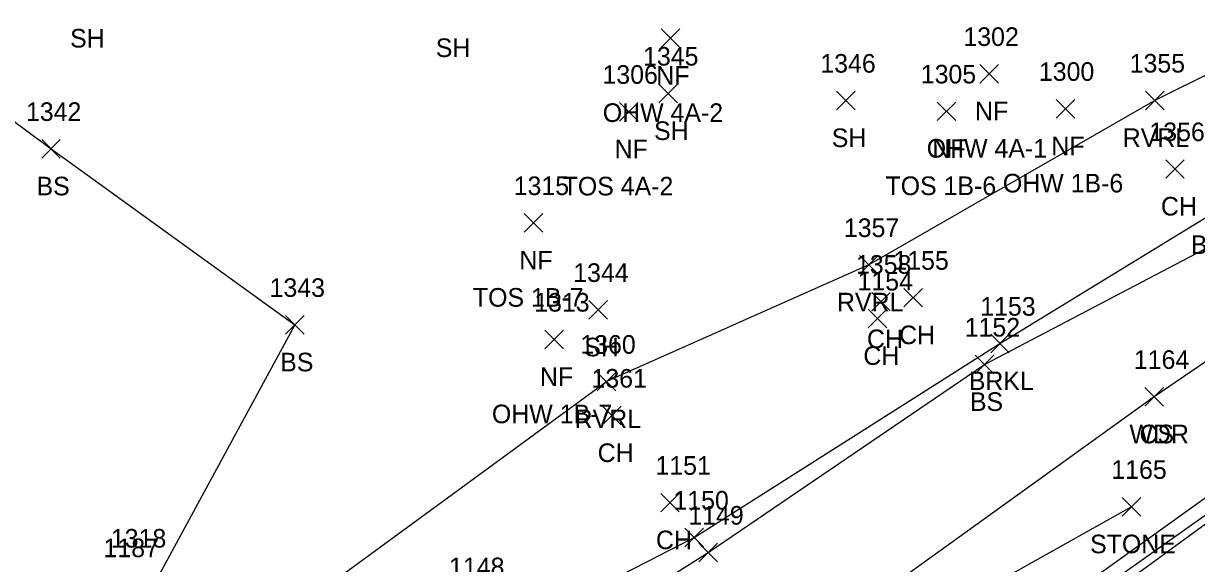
# Model space of a CAD drawing. Extents: x 1528286 to 1556263, y 492387 to 508952.
# Drawn here: x 1528684.2 to 1528810.2, y 492907.5 to 492965.5 of the extents above; entities that cross this region are included whole.
import ezdxf

# ---------------------------------------------------------------- set-up
doc = ezdxf.new("R2010")
doc.units = 0
for name, color, linetype in [('L_A', 7, 'Continuous'), ('L_C', 7, 'Continuous'), ('L_I', 7, 'Continuous'), ('L_TIC', 7, 'Continuous'), ('LASF', 7, 'Continuous'), ('LAWA', 7, 'Continuous'), ('LAWE', 7, 'Continuous'), ('LELB', 7, 'Continuous'), ('PET', 7, 'Continuous'), ('RGR', 7, 'Continuous')]:
    doc.layers.add(name, color=color, linetype=linetype)

msp = doc.modelspace()

# ---------------------------------------------------------------- linework, layer by layer
at = {"layer": 'L_TIC'}
for points in [[(1528752.67, 492962.95), (1528754.67, 492964.95)], [(1528754.67, 492962.95), (1528752.67, 492964.95)], [(1528752.67, 492962.95), (1528754.67, 492964.95)], [(1528754.67, 492962.95), (1528752.67, 492964.95)], [(1528786.91, 492959.12), (1528788.91, 492961.12)], [(1528788.91, 492959.12), (1528786.91, 492961.12)], [(1528786.91, 492959.12), (1528788.91, 492961.12)], [(1528788.91, 492959.12), (1528786.91, 492961.12)], [(1528752.42, 492957.01), (1528754.42, 492959.01)], [(1528754.42, 492957.01), (1528752.42, 492959.01)], [(1528752.42, 492957.01), (1528754.42, 492959.01)], [(1528754.42, 492957.01), (1528752.42, 492959.01)], [(1528771.51, 492956.25), (1528773.51, 492958.25)], [(1528773.51, 492956.25), (1528771.51, 492958.25)], [(1528771.51, 492956.25), (1528773.51, 492958.25)], [(1528773.51, 492956.25), (1528771.51, 492958.25)], [(1528804.69, 492956.26), (1528806.69, 492958.26)], [(1528806.69, 492956.26), (1528804.69, 492958.26)], [(1528804.69, 492956.26), (1528806.69, 492958.26)], [(1528806.69, 492956.26), (1528804.69, 492958.26)], [(1528748.19, 492955.05), (1528750.19, 492957.05)], [(1528750.19, 492955.05), (1528748.19, 492957.05)], [(1528748.19, 492955.05), (1528750.19, 492957.05)], [(1528750.19, 492955.05), (1528748.19, 492957.05)], [(1528782.33, 492955.09), (1528784.33, 492957.09)], [(1528784.33, 492955.09), (1528782.33, 492957.09)], [(1528782.33, 492955.09), (1528784.33, 492957.09)], [(1528784.33, 492955.09), (1528782.33, 492957.09)], [(1528795.11, 492955.37), (1528797.11, 492957.37)], [(1528797.11, 492955.37), (1528795.11, 492957.37)], [(1528795.11, 492955.37), (1528797.11, 492957.37)], [(1528797.11, 492955.37), (1528795.11, 492957.37)], [(1528686.13, 492951.06), (1528688.13, 492953.06)], [(1528688.13, 492951.06), (1528686.13, 492953.06)], [(1528686.13, 492951.06), (1528688.13, 492953.06)], [(1528688.13, 492951.06), (1528686.13, 492953.06)], [(1528806.87, 492948.89), (1528808.87, 492950.89)], [(1528808.87, 492948.89), (1528806.87, 492950.89)], [(1528806.87, 492948.89), (1528808.87, 492950.89)], [(1528808.87, 492948.89), (1528806.87, 492950.89)], [(1528737.96, 492943.09), (1528739.96, 492945.09)], [(1528739.96, 492943.09), (1528737.96, 492945.09)], [(1528737.96, 492943.09), (1528739.96, 492945.09)], [(1528739.96, 492943.09), (1528737.96, 492945.09)], [(1528773.99, 492938.58), (1528775.99, 492940.58)], [(1528775.99, 492938.58), (1528773.99, 492940.58)], [(1528773.99, 492938.58), (1528775.99, 492940.58)], [(1528775.99, 492938.58), (1528773.99, 492940.58)], [(1528775.29, 492934.63), (1528777.29, 492936.63)], [(1528777.29, 492934.63), (1528775.29, 492936.63)], [(1528775.29, 492934.63), (1528777.29, 492936.63)], [(1528777.29, 492934.63), (1528775.29, 492936.63)], [(1528778.74, 492935.06), (1528780.74, 492937.06)], [(1528780.74, 492935.06), (1528778.74, 492937.06)], [(1528778.74, 492935.06), (1528780.74, 492937.06)], [(1528780.74, 492935.06), (1528778.74, 492937.06)], [(1528744.92, 492933.75), (1528746.92, 492935.75)], [(1528746.92, 492933.75), (1528744.92, 492935.75)], [(1528744.92, 492933.75), (1528746.92, 492935.75)], [(1528746.92, 492933.75), (1528744.92, 492935.75)], [(1528712.31, 492932.14), (1528714.31, 492934.14)], [(1528714.31, 492932.14), (1528712.31, 492934.14)], [(1528712.31, 492932.14), (1528714.31, 492934.14)], [(1528714.31, 492932.14), (1528712.31, 492934.14)], [(1528774.9, 492932.83), (1528776.9, 492934.83)], [(1528776.9, 492932.83), (1528774.9, 492934.83)], [(1528774.9, 492932.83), (1528776.9, 492934.83)], [(1528776.9, 492932.83), (1528774.9, 492934.83)], [(1528740.17, 492930.56), (1528742.17, 492932.56)], [(1528742.17, 492930.56), (1528740.17, 492932.56)], [(1528740.17, 492930.56), (1528742.17, 492932.56)], [(1528742.17, 492930.56), (1528740.17, 492932.56)], [(1528788.07, 492930.12), (1528790.07, 492932.12)], [(1528790.07, 492930.12), (1528788.07, 492932.12)], [(1528788.07, 492930.12), (1528790.07, 492932.12)], [(1528790.07, 492930.12), (1528788.07, 492932.12)], [(1528786.4, 492927.88), (1528788.4, 492929.88)], [(1528788.4, 492927.88), (1528786.4, 492929.88)], [(1528786.4, 492927.88), (1528788.4, 492929.88)], [(1528788.4, 492927.88), (1528786.4, 492929.88)], [(1528745.81, 492926.03), (1528747.81, 492928.03)], [(1528747.81, 492926.03), (1528745.81, 492928.03)], [(1528745.81, 492926.03), (1528747.81, 492928.03)], [(1528747.81, 492926.03), (1528745.81, 492928.03)], [(1528804.62, 492924.4), (1528806.62, 492926.4)], [(1528806.62, 492924.4), (1528804.62, 492926.4)], [(1528804.62, 492924.4), (1528806.62, 492926.4)], [(1528806.62, 492924.4), (1528804.62, 492926.4)], [(1528804.62, 492924.4), (1528806.62, 492926.4)], [(1528806.62, 492924.4), (1528804.62, 492926.4)], [(1528804.62, 492924.4), (1528806.62, 492926.4)], [(1528806.62, 492924.4), (1528804.62, 492926.4)], [(1528746.36, 492922.39), (1528748.36, 492924.39)], [(1528748.36, 492922.39), (1528746.36, 492924.39)], [(1528746.36, 492922.39), (1528748.36, 492924.39)], [(1528748.36, 492922.39), (1528746.36, 492924.39)], [(1528752.62, 492913.02), (1528754.62, 492915.02)], [(1528754.62, 492913.02), (1528752.62, 492915.02)], [(1528752.62, 492913.02), (1528754.62, 492915.02)], [(1528754.62, 492913.02), (1528752.62, 492915.02)], [(1528802.2, 492912.58), (1528804.2, 492914.58)], [(1528804.2, 492912.58), (1528802.2, 492914.58)], [(1528802.2, 492912.58), (1528804.2, 492914.58)], [(1528804.2, 492912.58), (1528802.2, 492914.58)], [(1528755.21, 492909.28), (1528757.21, 492911.28)], [(1528757.21, 492909.28), (1528755.21, 492911.28)], [(1528755.21, 492909.28), (1528757.21, 492911.28)], [(1528757.21, 492909.28), (1528755.21, 492911.28)], [(1528756.72, 492907.66), (1528758.72, 492909.66)], [(1528758.72, 492907.66), (1528756.72, 492909.66)], [(1528756.72, 492907.66), (1528758.72, 492909.66)], [(1528758.72, 492907.66), (1528756.72, 492909.66)]]:
    msp.add_lwpolyline(points, dxfattribs=at)
at = {"layer": 'LASF'}
msp.add_lwpolyline([(1528803.2, 492913.58), (1528764.36, 492891.78), (1528731.57, 492870.94), (1528716.56, 492864.1)], dxfattribs=at)
msp.add_lwpolyline([(1528803.2, 492913.58), (1528764.36, 492891.78), (1528731.57, 492870.94), (1528716.56, 492864.1)], dxfattribs=at)
at = {"layer": 'LAWA'}
msp.add_lwpolyline([(1528932.82, 493004.86), (1528877.3, 492973.44), (1528838.45, 492947.79), (1528805.62, 492925.4), (1528761.44, 492893.56), (1528731.58, 492876.41)], dxfattribs=at)
msp.add_lwpolyline([(1528932.82, 493004.86), (1528877.3, 492973.44), (1528838.45, 492947.79), (1528805.62, 492925.4), (1528761.44, 492893.56), (1528731.58, 492876.41)], dxfattribs=at)
at = {"layer": 'LAWE'}
for points in [[(1528718.66, 492995.48), (1528788.19, 492988.49), (1528851.65, 492980.15), (1528805.69, 492957.26), (1528774.99, 492939.58), (1528746.81, 492927.03)], [(1528718.66, 492995.48), (1528788.19, 492988.49), (1528851.65, 492980.15), (1528805.69, 492957.26), (1528774.99, 492939.58), (1528746.81, 492927.03)], [(1528699.7, 492858.91), (1528705.19, 492868.42), (1528711.6, 492880.33), (1528733.01, 492898.34), (1528756.21, 492910.28), (1528789.07, 492931.12), (1528812.92, 492945.76), (1528839.47, 492958.79)], [(1528699.7, 492858.91), (1528705.19, 492868.42), (1528711.6, 492880.33), (1528733.01, 492898.34), (1528756.21, 492910.28), (1528789.07, 492931.12), (1528812.92, 492945.76), (1528839.47, 492958.79)], [(1528693.76, 492868.56), (1528695.31, 492889.33), (1528746.81, 492927.03)]]:
    msp.add_lwpolyline(points, dxfattribs=at)
at = {"layer": 'LELB'}
for points in [[(1528932.82, 493004.86), (1528877.3, 492973.44), (1528838.45, 492947.79), (1528805.62, 492925.4)], [(1528932.82, 493004.86), (1528877.3, 492973.44), (1528838.45, 492947.79), (1528805.62, 492925.4)], [(1528511.53, 492702.85), (1528534.14, 492721.31), (1528572.64, 492751.16), (1528586.73, 492763.59), (1528600.5, 492766.35), (1528613.46, 492775.52), (1528652.2, 492802.53), (1528688.62, 492828.26), (1528710.29, 492843.12), (1528742.91, 492866.47), (1528778.71, 492891.27), (1528817.45, 492919.08), (1528857.75, 492946.94), (1528897.37, 492973.98), (1528940.29, 493003.74)], [(1528511.53, 492702.85), (1528534.14, 492721.31), (1528572.64, 492751.16), (1528586.73, 492763.59), (1528600.5, 492766.35), (1528613.46, 492775.52), (1528652.2, 492802.53), (1528688.62, 492828.26), (1528710.29, 492843.12), (1528742.91, 492866.47), (1528778.71, 492891.27), (1528817.45, 492919.08), (1528857.75, 492946.94), (1528897.37, 492973.98), (1528940.29, 493003.74)], [(1528641.69, 492985.75), (1528687.13, 492952.06), (1528713.31, 492933.14), (1528693.78, 492897.09)], [(1528641.69, 492985.75), (1528687.13, 492952.06), (1528713.31, 492933.14), (1528693.78, 492897.09)], [(1528716.33, 492882.99), (1528739.42, 492897.09), (1528757.72, 492908.66), (1528787.4, 492928.88), (1528815.35, 492943.52), (1528839.47, 492958.79)], [(1528716.33, 492882.99), (1528739.42, 492897.09), (1528757.72, 492908.66), (1528787.4, 492928.88), (1528815.35, 492943.52), (1528839.47, 492958.79)]]:
    msp.add_lwpolyline(points, dxfattribs=at)
at = {"layer": 'PET'}
msp.add_lwpolyline([(1528942, 493002.12), (1528898.48, 492972.51), (1528859.28, 492945.34), (1528819.08, 492917.53), (1528787.55, 492894.48), (1528780.46, 492889.94), (1528744.23, 492865.12), (1528711.17, 492841.82), (1528689.56, 492826.66), (1528653.33, 492801.52)], dxfattribs=at)
msp.add_lwpolyline([(1528942, 493002.12), (1528898.48, 492972.51), (1528859.28, 492945.34), (1528819.08, 492917.53), (1528787.55, 492894.48), (1528780.46, 492889.94), (1528744.23, 492865.12), (1528711.17, 492841.82), (1528689.56, 492826.66), (1528653.33, 492801.52)], dxfattribs=at)
at = {"layer": 'RGR'}
msp.add_lwpolyline([(1528941.4, 493002.79), (1528898.12, 492973.22), (1528858.97, 492945.9), (1528818.83, 492918.12), (1528780.05, 492890.64), (1528744.15, 492865.31), (1528711.24, 492842.07), (1528689.6, 492826.87), (1528653.3, 492801.62)], dxfattribs=at)
msp.add_lwpolyline([(1528941.4, 493002.79), (1528898.12, 492973.22), (1528858.97, 492945.9), (1528818.83, 492918.12), (1528780.05, 492890.64), (1528744.15, 492865.31), (1528711.24, 492842.07), (1528689.6, 492826.87), (1528653.3, 492801.62)], dxfattribs=at)

# ---------------------------------------------------------------- texts
at = {"layer": 'L_A'}
for s, p in [('SH', (1528689.18, 492962.95)), ('SH', (1528689.18, 492962.95)), ('SH', (1528728.46, 492961.93)), ('SH', (1528728.46, 492961.93)), ('NF', (1528752.15, 492958.95)), ('NF', (1528752.15, 492958.95)), ('NF', (1528786.39, 492955.12)), ('NF', (1528786.39, 492955.12)), ('SH', (1528751.91, 492953.01)), ('SH', (1528751.91, 492953.01)), ('SH', (1528771, 492952.25)), ('SH', (1528771, 492952.25)), ('RVRL', (1528802.26, 492952.26)), ('RVRL', (1528802.26, 492952.26)), ('NF', (1528747.67, 492951.05)), ('NF', (1528747.67, 492951.05)), ('NF', (1528781.81, 492951.09)), ('NF', (1528781.81, 492951.09)), ('NF', (1528794.59, 492951.37)), ('NF', (1528794.59, 492951.37)), ('BS', (1528685.57, 492947.06)), ('BS', (1528685.57, 492947.06)), ('CH', (1528806.36, 492944.89)), ('CH', (1528806.36, 492944.89)), ('BRKL', (1528809.57, 492940.76)), ('BRKL', (1528809.57, 492940.76)), ('NF', (1528737.44, 492939.09)), ('NF', (1528737.44, 492939.09)), ('RVRL', (1528771.56, 492934.58)), ('RVRL', (1528771.56, 492934.58)), ('CH', (1528778.23, 492931.06)), ('CH', (1528778.23, 492931.06)), ('SH', (1528744.41, 492929.75)), ('SH', (1528744.41, 492929.75)), ('CH', (1528774.78, 492930.63)), ('CH', (1528774.78, 492930.63)), ('CH', (1528774.39, 492928.83)), ('CH', (1528774.39, 492928.83)), ('BS', (1528711.75, 492928.14)), ('BS', (1528711.75, 492928.14)), ('NF', (1528739.65, 492926.56)), ('NF', (1528739.65, 492926.56)), ('BRKL', (1528785.72, 492926.12)), ('BRKL', (1528785.72, 492926.12)), ('BS', (1528785.84, 492923.88)), ('BS', (1528785.84, 492923.88)), ('RVRL', (1528743.38, 492922.03)), ('RVRL', (1528743.38, 492922.03)), ('WDR', (1528802.98, 492920.4)), ('WDR', (1528802.98, 492920.4)), ('CS', (1528804.06, 492920.4)), ('CS', (1528804.06, 492920.4)), ('CH', (1528745.85, 492918.39)), ('CH', (1528745.85, 492918.39)), ('CH', (1528752.11, 492909.02)), ('CH', (1528752.11, 492909.02)), ('STONE', (1528798.75, 492908.58)), ('STONE', (1528798.75, 492908.58))]:
    msp.add_text(s, height=2, dxfattribs=at).set_placement(p)
at = {"layer": 'L_C'}
for s, p in [('OHW 4A-2', (1528746.4, 492954.95)), ('OHW 4A-2', (1528746.4, 492954.95)), ('OHW 4A-1', (1528781.2, 492951.12)), ('OHW 4A-1', (1528781.2, 492951.12)), ('TOS 1B-6', (1528776.77, 492947.09)), ('TOS 1B-6', (1528776.77, 492947.09)), ('OHW 1B-6', (1528789.38, 492947.37)), ('OHW 1B-6', (1528789.38, 492947.37)), ('TOS 4A-2', (1528742.09, 492947.05)), ('TOS 4A-2', (1528742.09, 492947.05)), ('TOS 1B-7', (1528732.45, 492935.09)), ('TOS 1B-7', (1528732.45, 492935.09)), ('OHW 1B-7', (1528734.49, 492922.56)), ('OHW 1B-7', (1528734.49, 492922.56))]:
    msp.add_text(s, height=2, dxfattribs=at).set_placement(p)
at = {"layer": 'L_I'}
for s, p in [('1302', (1528785.14, 492963.12)), ('1302', (1528785.14, 492963.12)), ('1345', (1528750.73, 492961.01)), ('1345', (1528750.73, 492961.01)), ('1346', (1528769.77, 492960.25)), ('1346', (1528769.77, 492960.25)), ('1355', (1528803, 492960.26)), ('1355', (1528803, 492960.26)), ('1306', (1528746.37, 492959.05)), ('1306', (1528746.37, 492959.05)), ('1305', (1528780.56, 492959.09)), ('1305', (1528780.56, 492959.09)), ('1300', (1528793.25, 492959.37)), ('1300', (1528793.25, 492959.37)), ('1342', (1528684.44, 492955.06)), ('1342', (1528684.44, 492955.06)), ('1356', (1528805.12, 492952.89)), ('1356', (1528805.12, 492952.89)), ('1315', (1528736.83, 492947.09)), ('1315', (1528736.83, 492947.09)), ('1357', (1528772.3, 492942.58)), ('1357', (1528772.3, 492942.58)), ('1358', (1528773.6, 492938.63)), ('1358', (1528773.6, 492938.63)), ('1155', (1528777.62, 492939.06)), ('1155', (1528777.62, 492939.06)), ('1344', (1528743.23, 492937.75)), ('1344', (1528743.23, 492937.75)), ('1343', (1528710.61, 492936.14)), ('1343', (1528710.61, 492936.14)), ('1154', (1528773.77, 492936.83)), ('1154', (1528773.77, 492936.83)), ('1313', (1528739.04, 492934.56)), ('1313', (1528739.04, 492934.56)), ('1153', (1528786.95, 492934.12)), ('1153', (1528786.95, 492934.12)), ('1152', (1528785.28, 492931.88)), ('1152', (1528785.28, 492931.88)), ('1360', (1528743.99, 492930.03)), ('1360', (1528743.99, 492930.03)), ('1164', (1528803.45, 492928.4)), ('1164', (1528803.45, 492928.4)), ('1164', (1528803.45, 492928.4)), ('1164', (1528803.45, 492928.4)), ('1361', (1528745.19, 492926.39)), ('1361', (1528745.19, 492926.39)), ('1151', (1528752.06, 492917.02)), ('1151', (1528752.06, 492917.02)), ('1165', (1528801.03, 492916.58)), ('1165', (1528801.03, 492916.58)), ('1150', (1528753.99, 492913.28)), ('1150', (1528753.99, 492913.28)), ('1149', (1528755.59, 492911.66)), ('1149', (1528755.59, 492911.66)), ('1187', (1528692.77, 492908.16)), ('1187', (1528692.77, 492908.16)), ('1318', (1528693.56, 492909.19)), ('1318', (1528693.56, 492909.19)), ('1148', (1528729.89, 492906.11)), ('1148', (1528729.89, 492906.11))]:
    msp.add_text(s, height=2, dxfattribs=at).set_placement(p)

doc.saveas('drawing.dxf')
